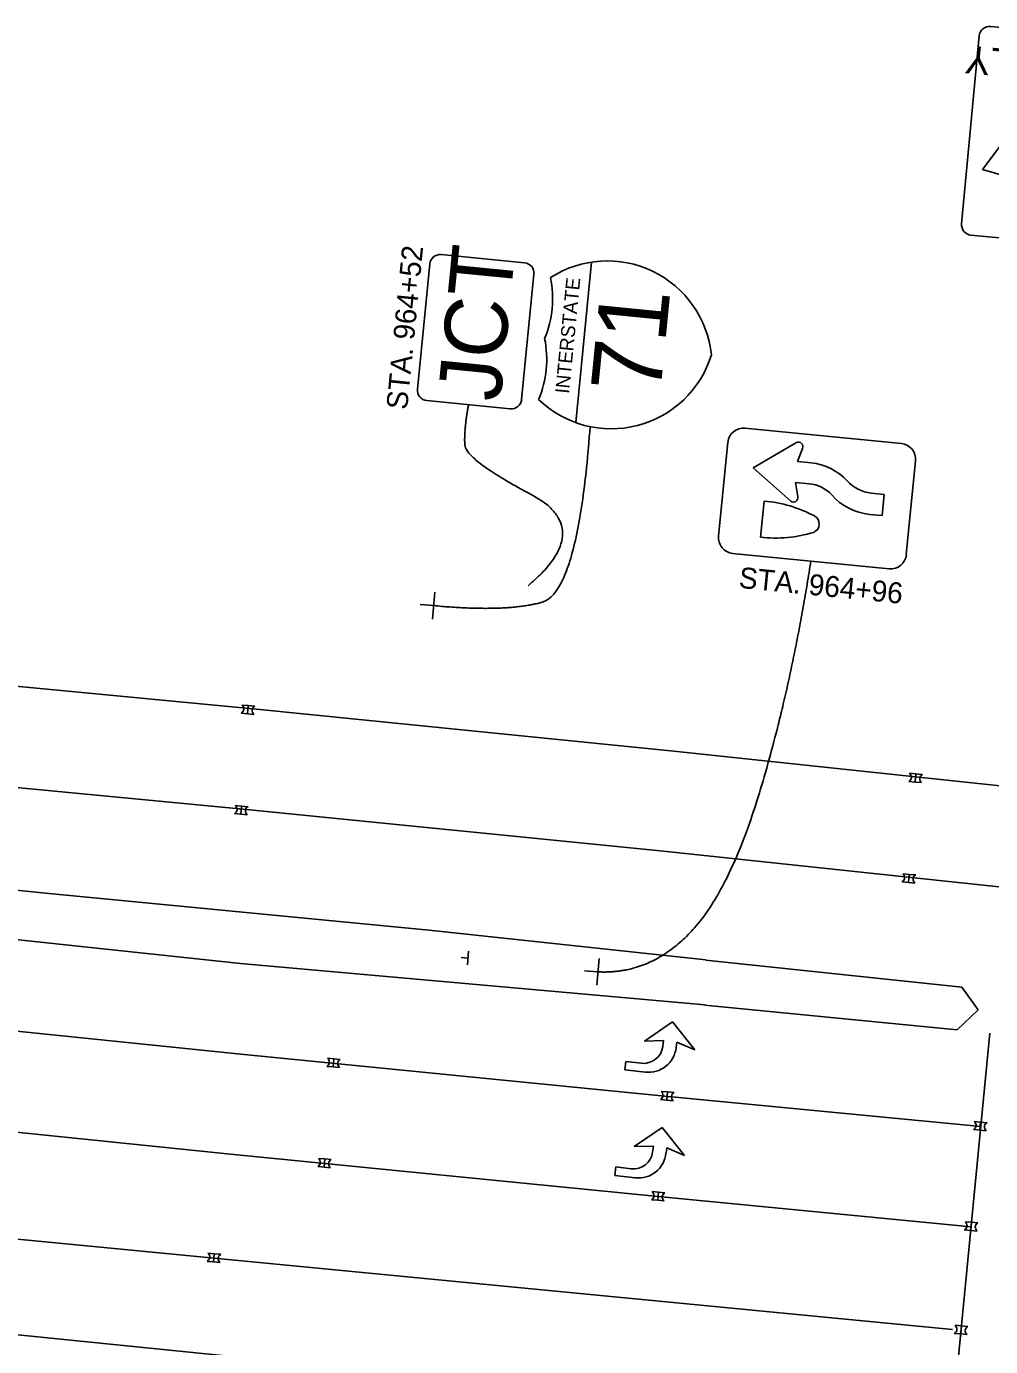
# Model space of a CAD drawing. Extents: x 1847379 to 1850904, y 217032 to 220169.
# Drawn here: x 1850540.3 to 1850655.3, y 218683.8 to 218841.3 of the extents above; entities that cross this region are included whole.
import ezdxf

# ---------------------------------------------------------------- set-up
doc = ezdxf.new("R2010")
doc.units = 0
for name, color, linetype in [('PM_P_Cells', 7, 'Continuous'), ('PM_P_Channelizing_Line', 7, 'Continuous'), ('PM_P_CL_Double_Solid', 7, 'Continuous'), ('PM_P_Edge_Line', 7, 'Continuous'), ('PM_P_Lane_Line', 7, 'Continuous'), ('PM_P_Stop_Line', 7, 'Continuous'), ('SN_P_Signs', 7, 'Continuous'), ('SN_X_Public', 7, 'Continuous')]:
    doc.layers.add(name, color=color, linetype=linetype)

msp = doc.modelspace()

# ---------------------------------------------------------------- linework, layer by layer
at = {"layer": 'PM_P_Cells'}
for p, q in [((1850565.91, 218759.37), (1850566.68, 218759.3)), ((1850565.91, 218759.37), (1850566.68, 218759.3)), ((1850566.76, 218760.27), (1850566, 218760.34)), ((1850566, 218760.34), (1850566.76, 218760.27)), ((1850566.68, 218759.3), (1850566.76, 218760.27)), ((1850566.68, 218759.3), (1850567.44, 218759.23)), ((1850566.76, 218760.27), (1850567.53, 218760.2)), ((1850645.54, 218751.23), (1850646.31, 218751.16)), ((1850645.54, 218751.23), (1850646.31, 218751.16)), ((1850646.4, 218752.13), (1850645.63, 218752.2)), ((1850645.63, 218752.2), (1850646.4, 218752.13)), ((1850646.31, 218751.16), (1850646.4, 218752.13)), ((1850646.31, 218751.16), (1850647.08, 218751.09)), ((1850646.4, 218752.13), (1850647.17, 218752.06)), ((1850565.96, 218748.29), (1850565.2, 218748.36)), ((1850565.2, 218748.36), (1850565.96, 218748.29)), ((1850565.88, 218747.32), (1850565.96, 218748.29)), ((1850565.96, 218748.29), (1850566.73, 218748.22)), ((1850565.11, 218747.39), (1850565.88, 218747.32)), ((1850565.11, 218747.39), (1850565.88, 218747.32)), ((1850565.88, 218747.32), (1850566.64, 218747.25)), ((1850645.6, 218740.15), (1850644.83, 218740.22)), ((1850644.83, 218740.22), (1850645.6, 218740.15)), ((1850645.51, 218739.17), (1850645.6, 218740.15)), ((1850645.6, 218740.15), (1850646.37, 218740.08)), ((1850644.74, 218739.24), (1850645.51, 218739.17)), ((1850644.74, 218739.24), (1850645.51, 218739.17)), ((1850645.51, 218739.17), (1850646.28, 218739.1)), ((1850617.35, 218722.55), (1850614.02, 218720.26)), ((1850620.02, 218719.21), (1850617.35, 218722.55)), ((1850612.07, 218720.16), (1850612.07, 218720.16)), ((1850614.02, 218720.26), (1850616.28, 218720.33)), ((1850616.28, 218720.33), (1850616.2, 218719.63)), ((1850617.79, 218719.48), (1850617.87, 218720.14)), ((1850617.87, 218720.14), (1850620.02, 218719.21)), ((1850576.97, 218718.15), (1850576.21, 218718.22)), ((1850576.21, 218718.22), (1850576.97, 218718.15)), ((1850576.89, 218717.18), (1850576.97, 218718.15)), ((1850576.97, 218718.15), (1850577.74, 218718.08)), ((1850620.02, 218719.21), (1850620.02, 218719.21)), ((1850576.12, 218717.25), (1850576.89, 218717.18)), ((1850576.12, 218717.25), (1850576.89, 218717.18)), ((1850576.89, 218717.18), (1850577.65, 218717.11)), ((1850611.79, 218717.84), (1850611.68, 218716.85)), ((1850611.68, 218716.85), (1850614.14, 218716.56)), ((1850613.64, 218717.62), (1850611.79, 218717.84)), ((1850615.92, 218713.29), (1850616.69, 218713.22)), ((1850615.92, 218713.29), (1850616.69, 218713.22)), ((1850616.78, 218714.19), (1850616.01, 218714.26)), ((1850616.01, 218714.26), (1850616.78, 218714.19)), ((1850616.69, 218713.22), (1850616.78, 218714.19)), ((1850616.69, 218713.22), (1850617.46, 218713.15)), ((1850616.78, 218714.19), (1850617.55, 218714.12)), ((1850654.11, 218710.6), (1850653.34, 218710.67)), ((1850653.34, 218710.67), (1850654.11, 218710.6)), ((1850654.02, 218709.63), (1850654.11, 218710.6)), ((1850654.11, 218710.6), (1850654.88, 218710.53)), ((1850616.15, 218709.95), (1850612.81, 218707.67)), ((1850618.81, 218706.61), (1850616.15, 218709.95)), ((1850653.26, 218709.7), (1850654.02, 218709.63)), ((1850653.26, 218709.7), (1850654.02, 218709.63)), ((1850654.02, 218709.63), (1850654.79, 218709.56)), ((1850610.87, 218707.56), (1850610.87, 218707.56)), ((1850612.81, 218707.67), (1850615.08, 218707.73)), ((1850615.08, 218707.73), (1850614.99, 218707.03)), ((1850616.59, 218706.88), (1850616.67, 218707.54)), ((1850616.67, 218707.54), (1850618.81, 218706.61)), ((1850575.04, 218705.29), (1850575.81, 218705.22)), ((1850575.04, 218705.29), (1850575.81, 218705.22)), ((1850575.89, 218706.2), (1850575.13, 218706.27)), ((1850575.13, 218706.27), (1850575.89, 218706.2)), ((1850575.81, 218705.22), (1850575.89, 218706.2)), ((1850575.89, 218706.2), (1850576.66, 218706.13)), ((1850618.81, 218706.61), (1850618.81, 218706.61)), ((1850575.81, 218705.22), (1850576.57, 218705.15)), ((1850610.59, 218705.25), (1850610.47, 218704.25)), ((1850610.47, 218704.25), (1850612.93, 218703.96)), ((1850612.44, 218705.03), (1850610.59, 218705.25)), ((1850615.7, 218702.24), (1850614.93, 218702.31)), ((1850614.93, 218702.31), (1850615.7, 218702.24)), ((1850615.61, 218701.27), (1850615.7, 218702.24)), ((1850615.7, 218702.24), (1850616.46, 218702.17)), ((1850614.84, 218701.34), (1850615.61, 218701.27)), ((1850614.84, 218701.34), (1850615.61, 218701.27)), ((1850615.61, 218701.27), (1850616.38, 218701.2)), ((1850652.17, 218697.75), (1850652.94, 218697.68)), ((1850652.17, 218697.75), (1850652.94, 218697.68)), ((1850653.03, 218698.65), (1850652.26, 218698.72)), ((1850652.26, 218698.72), (1850653.03, 218698.65)), ((1850652.94, 218697.68), (1850653.03, 218698.65)), ((1850652.94, 218697.68), (1850653.71, 218697.61)), ((1850653.03, 218698.65), (1850653.8, 218698.58)), ((1850562.71, 218694.9), (1850561.95, 218694.97)), ((1850561.95, 218694.97), (1850562.71, 218694.9)), ((1850562.63, 218693.93), (1850562.71, 218694.9)), ((1850562.71, 218694.9), (1850563.48, 218694.83)), ((1850561.86, 218693.99), (1850562.63, 218693.93)), ((1850561.86, 218693.99), (1850562.63, 218693.93)), ((1850562.63, 218693.93), (1850563.39, 218693.86)), ((1850651.84, 218686.3), (1850651.07, 218686.37)), ((1850651.07, 218686.37), (1850651.84, 218686.3)), ((1850650.98, 218685.4), (1850651.75, 218685.33)), ((1850650.98, 218685.4), (1850651.75, 218685.33)), ((1850651.75, 218685.33), (1850651.84, 218686.3)), ((1850651.75, 218685.33), (1850652.52, 218685.26)), ((1850651.84, 218686.3), (1850652.6, 218686.23))]:
    msp.add_line(p, q, dxfattribs=at)
for centre, radius, start, end in [((1850565.65, 218759.88), 0.576, 296.8063, 52.8586), ((1850565.65, 218759.88), 0.576, 296.8063, 52.8586), ((1850567.79, 218759.69), 0.576, 116.8063, 232.8586), ((1850645.28, 218751.74), 0.576, 296.8063, 52.8586), ((1850645.28, 218751.74), 0.576, 296.8063, 52.8586), ((1850647.43, 218751.55), 0.576, 116.8063, 232.8586), ((1850564.85, 218747.9), 0.576, 296.8063, 52.8586), ((1850564.85, 218747.9), 0.576, 296.8063, 52.8586), ((1850566.99, 218747.71), 0.576, 116.8063, 232.8586), ((1850644.48, 218739.76), 0.576, 296.8063, 52.8586), ((1850644.48, 218739.76), 0.576, 296.8063, 52.8586), ((1850646.63, 218739.56), 0.576, 116.8063, 232.8586), ((1850613.92, 218719.9), 2.3, 263.1824, 353.1824), ((1850614.53, 218719.82), 3.28, 263.1824, 354.0909), ((1850575.86, 218717.76), 0.576, 296.8063, 52.8586), ((1850575.86, 218717.76), 0.576, 296.8063, 52.8586), ((1850578, 218717.57), 0.576, 116.8063, 232.8586), ((1850615.66, 218713.8), 0.576, 296.8063, 52.8586), ((1850615.66, 218713.8), 0.576, 296.8063, 52.8586), ((1850617.81, 218713.61), 0.576, 116.8063, 232.8586), ((1850653, 218710.21), 0.576, 296.8063, 52.8586), ((1850653, 218710.21), 0.576, 296.8063, 52.8586), ((1850655.14, 218710.02), 0.576, 116.8063, 232.8586), ((1850612.71, 218707.31), 2.3, 263.1824, 353.1824), ((1850613.32, 218707.22), 3.28, 263.1824, 354.0909), ((1850574.78, 218705.81), 0.576, 296.8063, 52.8586), ((1850574.78, 218705.81), 0.576, 296.8063, 52.8586), ((1850576.92, 218705.61), 0.576, 116.8063, 232.8586), ((1850614.58, 218701.85), 0.576, 296.8063, 52.8586), ((1850614.58, 218701.85), 0.576, 296.8063, 52.8586), ((1850616.72, 218701.66), 0.576, 116.8063, 232.8586), ((1850651.92, 218698.26), 0.576, 296.8063, 52.8586), ((1850651.92, 218698.26), 0.576, 296.8063, 52.8586), ((1850654.06, 218698.07), 0.576, 116.8063, 232.8586), ((1850561.6, 218694.51), 0.576, 296.8063, 52.8586), ((1850561.6, 218694.51), 0.576, 296.8063, 52.8586), ((1850563.74, 218694.31), 0.576, 116.8063, 232.8586), ((1850650.72, 218685.91), 0.576, 296.8063, 52.8586), ((1850650.72, 218685.91), 0.576, 296.8063, 52.8586), ((1850652.86, 218685.72), 0.576, 116.8063, 232.8586)]:
    msp.add_arc(centre, radius, start, end, dxfattribs=at)
at = {"layer": 'PM_P_Channelizing_Line'}
for points in [[(1850652.98, 218698.12), (1850615.27, 218701.75), (1850564.66, 218706.78), (1850513.12, 218712.05), (1850461.3, 218717.14), (1850408.88, 218722.34), (1850360.86, 218727.03), (1850313.39, 218731.82), (1850265.8, 218736.37), (1849979.48, 218762.27)], [(1850654.14, 218710.06), (1850616.44, 218713.69), (1850565.86, 218718.72), (1850514.32, 218723.99), (1850462.47, 218729.08), (1850410.06, 218734.29), (1850362.04, 218738.97), (1850314.56, 218743.77), (1850266.91, 218748.32), (1850234.59, 218751.24)], [(1850650.65, 218674.09), (1850566.02, 218682.53), (1850518.02, 218687.39), (1850471.03, 218692.07), (1850419.06, 218697.16), (1850371.65, 218702.19), (1850311.6, 218707.75), (1850264.65, 218712.06), (1850215.84, 218717), (1850171.13, 218721.51), (1850121.19, 218725.85), (1850066.37, 218730.8), (1850014.99, 218735.41), (1849965.69, 218739.72), (1849914.21, 218744.36), (1849896.49, 218746.14)]]:
    msp.add_lwpolyline(points, dxfattribs=at)
at = {"layer": 'PM_P_CL_Double_Solid'}
for p, q in [((1850621.34, 218729.92), (1850651.86, 218726.7)), ((1850651.86, 218726.7), (1850653.84, 218723.97)), ((1850651.34, 218721.59), (1850621.22, 218724.56)), ((1850653.84, 218723.97), (1850651.34, 218721.59))]:
    msp.add_line(p, q, dxfattribs=at)
at = {"layer": 'PM_P_Edge_Line'}
for p, q in [((1850494.86, 218742.76), (1850542.59, 218737.91)), ((1850542.59, 218737.91), (1850588.33, 218733.5)), ((1850565.85, 218729.5), (1850516.36, 218734.8)), ((1850588.33, 218733.5), (1850621.34, 218729.94)), ((1850621.22, 218724.59), (1850565.85, 218729.5))]:
    msp.add_line(p, q, dxfattribs=at)
msp.add_lwpolyline([(1849889.22, 218821.46), (1849908.57, 218819.63), (1849959.34, 218815.75), (1850016.54, 218811.11), (1850069.2, 218806.62), (1850120.11, 218802.11), (1850169.53, 218797.86), (1850218.84, 218793.6), (1850268.16, 218788.98), (1850318.46, 218784.1), (1850367.53, 218779.29), (1850417.75, 218774.53), (1850467.84, 218769.49), (1850519.01, 218764.5), (1850567.74, 218759.83), (1850617.52, 218754.84), (1850666.94, 218749.6)], dxfattribs=at)
at = {"layer": 'PM_P_Lane_Line'}
msp.add_line((1849881.96, 218760.04), (1850650.78, 218685.87), dxfattribs=at)
msp.add_lwpolyline([(1849608.99, 218828.81), (1849660.31, 218825.18), (1849710.18, 218821.58), (1849761.09, 218817.87), (1849808.06, 218814.41), (1849858.45, 218811.1), (1849907.69, 218807.67), (1849958.4, 218803.79), (1850015.55, 218799.15), (1850068.16, 218794.66), (1850119.07, 218790.16), (1850168.5, 218785.91), (1850217.76, 218781.65), (1850267.02, 218777.03), (1850317.3, 218772.15), (1850366.38, 218767.35), (1850416.59, 218762.59), (1850466.65, 218757.55), (1850517.86, 218752.55), (1850566.57, 218747.88), (1850616.29, 218742.91), (1850664.9, 218737.75)], dxfattribs=at)
at = {"layer": 'PM_P_Stop_Line'}
msp.add_lwpolyline([(1850648.99, 218657.16), (1850651.21, 218679.79), (1850655.22, 218721.21)], dxfattribs=at)
at = {"layer": 'SN_P_Signs'}
for p, q in [((1850593.02, 218730.97), (1850592.91, 218729.37)), ((1850592.97, 218730.17), (1850592.17, 218730.22))]:
    msp.add_line(p, q, dxfattribs=at)
at = {"layer": 'SN_X_Public'}
for p, q in [((1850657.25, 218828.07), (1850654.34, 218824.21)), ((1850654.34, 218824.21), (1850658.98, 218822.87)), ((1850605.84, 218794.03), (1850607.72, 218813.17)), ((1850632.15, 218791.65), (1850627, 218788.62)), ((1850632.28, 218789.38), (1850632.88, 218790.94)), ((1850633.89, 218789.23), (1850632.28, 218789.38)), ((1850627, 218788.62), (1850631.46, 218784.65)), ((1850632.31, 218785.21), (1850632.03, 218786.9)), ((1850632.03, 218786.9), (1850633.65, 218786.74)), ((1850642.62, 218785.47), (1850641.07, 218785.62)), ((1850628.3, 218784.67), (1850627.87, 218780.35)), ((1850628.3, 218784.67), (1850628.3, 218784.67)), ((1850642.37, 218782.94), (1850642.62, 218785.47)), ((1850640.87, 218783.08), (1850642.37, 218782.94)), ((1850589.01, 218773.79), (1850588.72, 218770.6)), ((1850588.87, 218772.2), (1850587.27, 218772.34)), ((1850608.61, 218730.11), (1850608.32, 218726.92)), ((1850608.47, 218728.52), (1850606.87, 218728.66))]:
    msp.add_line(p, q, dxfattribs=at)
for points in [[(1850697.62, 218837.31), (1850655.31, 218841.28)], [(1850653.95, 218840.15), (1850651.85, 218817.75)], [(1850652.97, 218816.39), (1850695.29, 218812.42)], [(1850599.72, 218813.09), (1850589.77, 218814.07)], [(1850588.4, 218812.95), (1850586.93, 218798.02)], [(1850599.37, 218796.79), (1850600.84, 218811.72)], [(1850588.05, 218796.65), (1850598.01, 218795.67)], [(1850626.01, 218793.36), (1850644.67, 218791.52)], [(1850622.86, 218780.48), (1850623.96, 218791.68)], [(1850646.36, 218789.47), (1850645.25, 218778.28)], [(1850643.2, 218776.6), (1850624.54, 218778.43)]]:
    msp.add_lwpolyline(points, dxfattribs=at)
for centre, radius, start, end in [((1850655.19, 218840.03), 1.25, 84.6423, 174.6423), ((1850653.09, 218817.63), 1.25, 174.6423, 264.6423), ((1850589.65, 218812.82), 1.25, 84.3781, 174.3781), ((1850599.6, 218811.84), 1.25, 354.3781, 84.3781), ((1850609.58, 218800.81), 12.5, 5.9151, 122.7092), ((1850590.57, 218808.87), 12.5, 337.3872, 11.3691), ((1850589.86, 218801.6), 12.5, 337.3872, 11.3691), ((1850610.07, 218805.79), 12.5, 226.0471, 342.8412), ((1850588.18, 218797.9), 1.25, 174.3781, 264.3781), ((1850598.13, 218796.92), 1.25, 264.3781, 354.3781), ((1850625.83, 218791.49), 1.88, 84.3781, 174.3781), ((1850632.38, 218791.16), 0.547, 335.8829, 114.4271), ((1850644.49, 218789.66), 1.88, 354.3781, 84.3781), ((1850633.19, 218782.39), 6.87, 43.26, 84.1496), ((1850633.2, 218782.39), 4.37, 43.7536, 84.1496), ((1850641.5, 218789.97), 4.37, 221.0302, 264.3781), ((1850627, 218769.28), 15.44, 61.8304, 85.1651), ((1850631.78, 218785.09), 0.547, 234.3291, 12.8734), ((1850641.54, 218789.92), 6.87, 221.0302, 264.3781), ((1850633.79, 218781.94), 1.08, 293.1952, 62.5322), ((1850629.6, 218796.26), 16, 263.7974, 286.7643), ((1850624.73, 218780.3), 1.88, 174.3781, 264.3781), ((1850643.39, 218778.46), 1.88, 264.3781, 354.3781)]:
    msp.add_arc(centre, radius, start, end, dxfattribs=at)
for points in [[(1850593.03, 218796.16), (1850592.48, 218793.12), (1850592.71, 218789.59), (1850608.22, 218781.36), (1850600.13, 218774.56)], [(1850588.87, 218772.2), (1850597.49, 218771.39), (1850606.11, 218773.82), (1850607.54, 218793.55)], [(1850608.47, 218728.52), (1850614.63, 218728.19), (1850624.21, 218738.08), (1850631.57, 218762.68), (1850633.87, 218777.51)]]:
    msp.add_open_spline(points, degree=2, dxfattribs=at)

# ---------------------------------------------------------------- texts
for s, height, rotation, p in [('ONLY', 3.333, 174.6423, (1850664.55, 218837.9)), ('STA. 964+52', 2.5, 84.3781, (1850585.71, 218795.5)), ('JCT', 7.5, 84.3781, (1850596.82, 218796.43)), ('INTERSTATE', 1.667, 84.3781, (1850605.02, 218797.43)), ('71', 8.333, 84.3781, (1850615.89, 218797.28)), ('STA. 964+96', 2.5, 354.3781, (1850625.2, 218774.33))]:
    msp.add_text(s, height=height, rotation=rotation, dxfattribs=at).set_placement(p)

doc.saveas('drawing.dxf')
